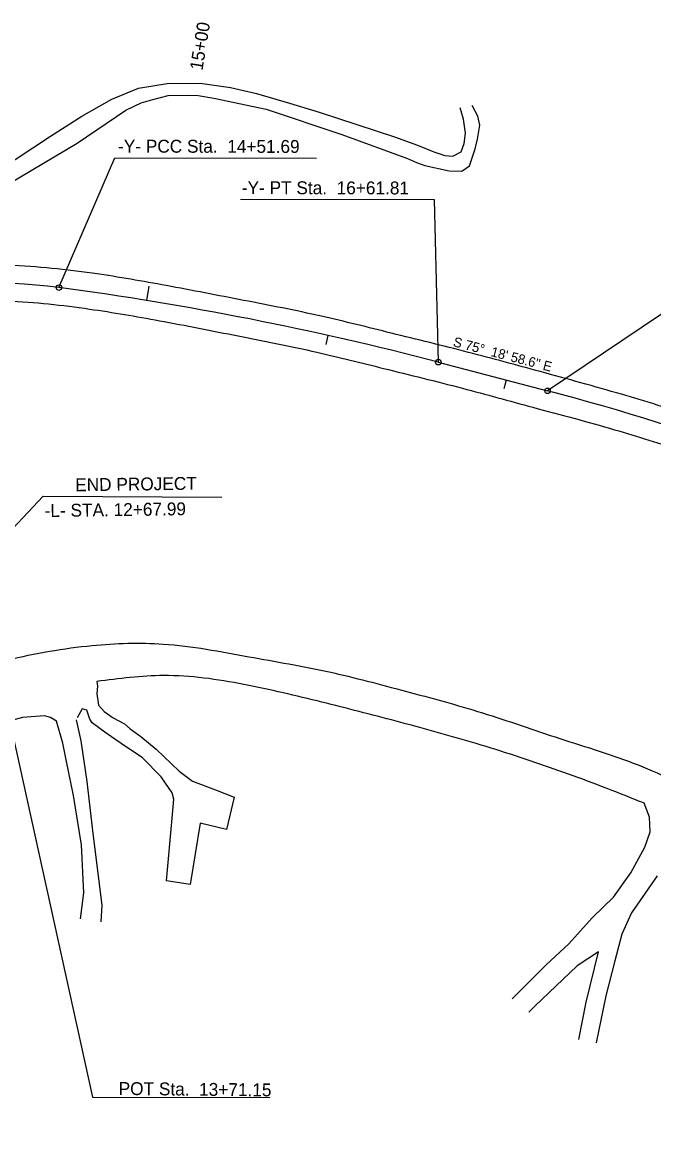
# Model space of a CAD drawing. Extents: x 757145 to 758829, y 592169 to 594973.
# Drawn here: x 757937 to 758280, y 594355 to 594960 of the extents above; entities that cross this region are included whole.
import ezdxf

# ---------------------------------------------------------------- set-up
doc = ezdxf.new("R2010")
doc.units = 0
for name, color, linetype in [('Default', 7, 'Continuous'), ('Exist Horizontal Alignment', 7, 'Continuous'), ('Exist Horizontal Alignment Direction Label', 7, 'Continuous'), ('Exist Horizontal Alignment Station Label', 7, 'Continuous'), ('Exist Horizontal Alignment Tick Label', 7, 'Continuous'), ('Exist Horizontal Alignment Tick Large', 7, 'Continuous'), ('Exist Horizontal Alignment Tick Small', 7, 'Continuous'), ('Prop Horizontal Alignment', 7, 'Continuous'), ('Prop Roadway Bridge', 7, 'Continuous')]:
    doc.layers.add(name, color=color, linetype=linetype)

msp = doc.modelspace()

# ---------------------------------------------------------------- linework, layer by layer
at = {"layer": 'Default'}
for p, q in [((757985.4, 594917.82), (757999.85, 594923.86)), ((757999.85, 594923.86), (758015.46, 594926.33)), ((758015.46, 594926.33), (758033.37, 594926.45)), ((758033.37, 594926.45), (758049.81, 594924.13)), ((758049.81, 594924.13), (758064.08, 594920.94)), ((758064.08, 594920.94), (758081.98, 594915.73)), ((757969.1, 594908.61), (757985.4, 594917.82)), ((757993.09, 594911.93), (758001.45, 594915.79)), ((758001.45, 594915.79), (758007.72, 594917.65)), ((758007.72, 594917.65), (758016.1, 594919.73)), ((758016.1, 594919.73), (758026.69, 594919.92)), ((758026.69, 594919.92), (758032.38, 594919.78)), ((758032.38, 594919.78), (758040.78, 594918.34)), ((758040.78, 594918.34), (758069.27, 594912.39)), ((758081.98, 594915.73), (758098.02, 594910.83)), ((757952.2, 594897.78), (757969.1, 594908.61)), ((757966.66, 594893.94), (757993.09, 594911.93)), ((758069.27, 594912.39), (758110.43, 594898.71)), ((758098.02, 594910.83), (758138.88, 594897.27)), ((758176.5, 594907.03), (758174.55, 594913.09)), ((758184.28, 594908.56), (758181.1, 594914.39)), ((758185.36, 594903.74), (758184.28, 594908.56)), ((758177.55, 594899.33), (758176.5, 594907.03)), ((758184.08, 594896.12), (758185.36, 594903.74)), ((757918.98, 594875.82), (757952.2, 594897.78)), ((758110.43, 594898.71), (758145.98, 594885.55)), ((758138.88, 594897.27), (758151.39, 594892.8)), ((758176.76, 594893.7), (758177.55, 594899.33)), ((757923.25, 594868.26), (757966.66, 594893.94)), ((758151.39, 594892.8), (758160.34, 594889.23)), ((758175.08, 594889.19), (758176.76, 594893.7)), ((758179.69, 594881.54), (758182.72, 594890.83)), ((758182.72, 594890.83), (758184.08, 594896.12)), ((758145.98, 594885.55), (758150.97, 594883.33)), ((758160.34, 594889.23), (758166.35, 594887.18)), ((758166.35, 594887.18), (758170.64, 594886.82)), ((758170.64, 594886.82), (758175.08, 594889.19)), ((758150.97, 594883.33), (758155.52, 594881.85)), ((758155.52, 594881.85), (758168.72, 594878.85)), ((758168.72, 594878.85), (758175.53, 594878.72)), ((758175.53, 594878.72), (758179.69, 594881.54)), ((757977.29, 594601.5), (757977.64, 594598.98)), ((757977.64, 594598.98), (757977.39, 594594.81)), ((757977.39, 594594.81), (757978.27, 594588.73)), ((757978.27, 594588.73), (757981.37, 594585.2)), ((757937.03, 594581.88), (757930.93, 594580.27)), ((757941.66, 594582.32), (757937.03, 594581.88)), ((757948.8, 594582.82), (757941.66, 594582.32)), ((757952.19, 594581.89), (757948.8, 594582.82)), ((757955.34, 594579.87), (757952.19, 594581.89)), ((757969.41, 594586.71), (757966.56, 594581.74)), ((757971.93, 594585.95), (757969.41, 594586.71)), ((757973.46, 594581.04), (757971.93, 594585.95)), ((757981.37, 594585.2), (757986.26, 594581.82)), ((757986.26, 594581.82), (757992.36, 594578.43)), ((757958.82, 594568.05), (757955.34, 594579.87)), ((757966.08, 594580.68), (757968.69, 594569.25)), ((757974.74, 594579.14), (757973.46, 594581.04)), ((757982.41, 594573.37), (757974.74, 594579.14)), ((757992.36, 594578.43), (757995.5, 594575.73)), ((757995.5, 594575.73), (758001.16, 594571.57)), ((757990.59, 594567.75), (757982.41, 594573.37)), ((758001.16, 594571.57), (758009.54, 594564.78)), ((757960.58, 594559.03), (757958.82, 594568.05)), ((757968.69, 594569.25), (757971.82, 594547.27)), ((758002.03, 594559.96), (757990.59, 594567.75)), ((758009.54, 594564.78), (758021.98, 594552.79)), ((757964.56, 594539.64), (757960.58, 594559.03)), ((758012.21, 594549.68), (758002.03, 594559.96)), ((758021.98, 594552.79), (758029.28, 594547.32)), ((757971.82, 594547.27), (757975.13, 594519.01)), ((758018.29, 594541.01), (758012.21, 594549.68)), ((758029.28, 594547.32), (758041.68, 594542.59)), ((757968.92, 594512.71), (757964.56, 594539.64)), ((758019.14, 594537.64), (758018.29, 594541.01)), ((758041.68, 594542.59), (758051.83, 594538.61)), ((758018.24, 594527.22), (758019.14, 594537.64)), ((758051.83, 594538.61), (758047.68, 594521.06)), ((758277.45, 594527.74), (758274.55, 594535.37)), ((758277.81, 594519.86), (758277.45, 594527.74)), ((758015.08, 594493.22), (758018.24, 594527.22)), ((758033.47, 594524.54), (758028.02, 594491.3)), ((758047.68, 594521.06), (758033.47, 594524.54)), ((757975.13, 594519.01), (757980.02, 594479.98)), ((758274.94, 594511.54), (758277.81, 594519.86)), ((757970.26, 594486.66), (757968.92, 594512.71)), ((758267.35, 594497.56), (758274.94, 594511.54)), ((758257.87, 594484.42), (758267.35, 594497.56)), ((758028.02, 594491.3), (758015.08, 594493.22)), ((758281.66, 594495.95), (758275.1, 594486.51)), ((757968.49, 594472.5), (757970.26, 594486.66)), ((758275.1, 594486.51), (758267.69, 594475.83)), ((757980.02, 594479.98), (757979.4, 594470.92)), ((758246.36, 594473.12), (758257.87, 594484.42)), ((758233.7, 594459.01), (758246.36, 594473.12)), ((758267.69, 594475.83), (758262.5, 594464.26)), ((758262.5, 594464.26), (758258.66, 594449.79)), ((758221.26, 594447.63), (758233.7, 594459.01)), ((758249.81, 594454.75), (758238.16, 594447.05)), ((758243.04, 594427.32), (758249.81, 594454.75)), ((758258.66, 594449.79), (758253.81, 594430.82)), ((758221.26, 594447.63), (758202.83, 594429.14)), ((758238.16, 594447.05), (758215.14, 594425.11)), ((758253.81, 594430.82), (758248.39, 594405.32)), ((758215.14, 594425.11), (758211.87, 594421.97)), ((758238.99, 594407.03), (758243.04, 594427.32))]:
    msp.add_line(p, q, dxfattribs=at)
for points in [[(758438.83, 594691.7), (758388.12, 594713.96), (758348.23, 594729.88), (758301, 594745.68), (758262.18, 594757.5), (758218.1, 594769.85), (758179.06, 594780.3), (758137.21, 594790.72), (758099.24, 594799.92), (758057.04, 594808.54), (758015.02, 594816.54), (757976.3, 594823.06), (757929.26, 594827.65), (757885.54, 594826.92), (757867.17, 594824.62)], [(757759.9, 594765.22), (757801.95, 594785.45), (757843.04, 594799.54), (757887.75, 594807.17), (757928.75, 594808.19), (757973.34, 594803.82), (758011.28, 594797.5), (758054.09, 594789.21), (758096.75, 594780.39), (758132.99, 594771.58), (758175.84, 594760.81), (758214.12, 594750.43), (758258.48, 594738.29), (758295.65, 594726.54), (758342.77, 594710.33), (758380.69, 594695.36), (758421.02, 594677.79), (758431.33, 594673.19)], [(757891.94, 594602.51), (757928.7, 594613.12), (757974.81, 594621.08), (758013.38, 594621.87), (758059.79, 594614.97), (758103.42, 594606.71), (758144.86, 594596.26), (758186.7, 594584.49), (758228.79, 594570.5), (758271.22, 594556.18), (758311.98, 594537.66), (758352.07, 594519.49), (758392.24, 594498.74), (758431.47, 594479.21), (758471.03, 594457.32), (758502.93, 594438.31), (758541.94, 594414.39), (758575.01, 594392.91), (758612.38, 594365.9), (758644.48, 594342.28), (758681.18, 594311.67), (758729.99, 594270.62), (758760.77, 594240.66)], [(758274.59, 594535.35), (758264.21, 594539.53), (758223.08, 594554.87), (758180.72, 594568.55), (758139.83, 594579.96), (758099.53, 594590.27), (758057.16, 594599.91), (758013.57, 594604.72), (757977.29, 594601.5)]]:
    msp.add_spline(points, degree=3, dxfattribs=at)
at = {"layer": 'Exist Horizontal Alignment'}
msp.add_line((758162.75, 594774.95), (758222.08, 594759.4), dxfattribs=at)
for centre, radius, start, end in [((757915.89, 594508.17), 310, 82.43399, 119.22975), ((757734.01, 593138.78), 1691.42, 75.31629, 82.43399), ((757905.22, 593550.23), 1250, 63.94354, 75.31629)]:
    msp.add_arc(centre, radius, start, end, dxfattribs=at)
at = {"layer": 'Exist Horizontal Alignment Station Label'}
for p, q in [((757956.71, 594815.47), (757987.03, 594886)), ((757987.03, 594886), (758096.57, 594885.8)), ((758055.3, 594863.45), (758160.51, 594863.26)), ((758160.51, 594863.26), (758162.75, 594774.95)), ((758323.31, 594827.62), (758222.08, 594759.4))]:
    msp.add_line(p, q, dxfattribs=at)
for centre in [(757956.71, 594815.47), (758162.75, 594774.95), (758222.08, 594759.4)]:
    msp.add_circle(centre, 1.5, dxfattribs=at)
at = {"layer": 'Exist Horizontal Alignment Tick Large'}
msp.add_line((758004.5, 594808.42), (758005.78, 594816.32), dxfattribs=at)
at = {"layer": 'Exist Horizontal Alignment Tick Small'}
for p, q in [((758102.68, 594789.52), (758101.59, 594784.64)), ((758199.69, 594765.27), (758198.42, 594760.43))]:
    msp.add_line(p, q, dxfattribs=at)
at = {"layer": 'Prop Horizontal Alignment'}
for q in [(758192.86, 594767.06), (758192.88, 594767.02)]:
    msp.add_line((758192.86, 594767.06), q, dxfattribs=at)
at = {"layer": 'Prop Roadway Bridge'}
for p, q in [((757826.37, 594572.61), (757948.13, 594702.11)), ((757948.13, 594702.11), (758045.11, 594701.68)), ((757925.05, 594602.71), (757974.94, 594375.77)), ((757974.94, 594375.77), (758071.24, 594375.6))]:
    msp.add_line(p, q, dxfattribs=at)

# ---------------------------------------------------------------- texts
at = {"layer": 'Exist Horizontal Alignment Direction Label'}
msp.add_text('S 75%%d  18\' 58.6" E', height=5.25, rotation=345.31629, dxfattribs=at).set_placement((758170.46, 594783.69))
at = {"layer": 'Exist Horizontal Alignment Station Label'}
for s, p in [('-Y- PCC Sta.  14+51.69', (757988.83, 594888.8)), ('-Y- PT Sta.  16+61.81', (758056.04, 594866.25))]:
    msp.add_text(s, height=7, rotation=359.89587, dxfattribs=at).set_placement(p)
at = {"layer": 'Exist Horizontal Alignment Tick Label'}
msp.add_text('15+00', height=7, rotation=80.79768, dxfattribs=at).set_placement((758034.66, 594933.15))
at = {"layer": 'Prop Roadway Bridge'}
for s, rotation, p in [('END PROJECT', 0.76053, (757965.6, 594704.8)), ('-L- STA. 12+67.99', 0.76053, (757949.02, 594690.81)), ('POT Sta.  13+71.15', 359.44276, (757989.13, 594376.94))]:
    msp.add_text(s, height=7, rotation=rotation, dxfattribs=at).set_placement(p)

doc.saveas('drawing.dxf')
